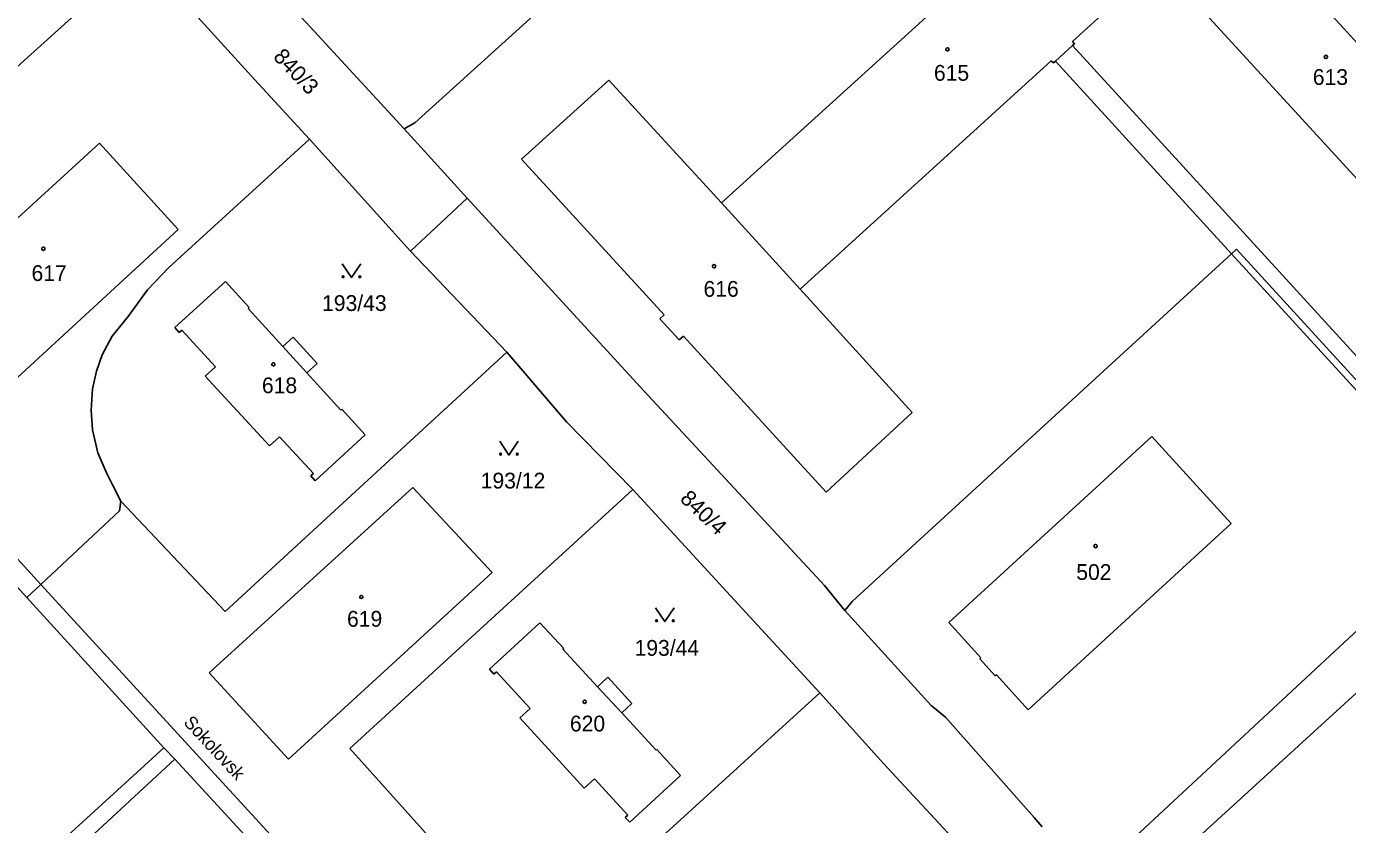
# Model space of a CAD drawing. Extents: x -735249 to -729401, y -1124843 to -1121828.
# Drawn here: x -733284.9 to -733142.5, y -1124173.7 to -1124087.8 of the extents above; entities that cross this region are included whole.
import ezdxf

# ---------------------------------------------------------------- set-up
doc = ezdxf.new("R2010")
doc.units = 0
for name, color, linetype in [('Vrstva 1', 7, 'Continuous'), ('Vrstva 15', 7, 'Continuous'), ('Vrstva 18', 7, 'Continuous'), ('Vrstva 19', 7, 'Continuous'), ('Vrstva 25', 7, 'Continuous'), ('Vrstva 4', 7, 'Continuous')]:
    doc.layers.add(name, color=color, linetype=linetype)

msp = doc.modelspace()

# ---------------------------------------------------------------- linework, layer by layer
at = {"layer": 'Vrstva 1'}
for points in [[(-733202.13, -1124061.12), (-733243.06, -1124098.12)], [(-733254.36, -1124087.81), (-733263.47, -1124077.99)], [(-733312.42, -1124115.94), (-733273.21, -1124080.62)], [(-733270.79, -1124081.95), (-733260.31, -1124093.51)], [(-733182.93, -1124082.16), (-733210.01, -1124106.74)], [(-733172.19, -1124089.37), (-733165.47, -1124083.25)], [(-733159.78, -1124084.25), (-733138.67, -1124107.29)], [(-733137.55, -1124093.86), (-733146.91, -1124083.63)], [(-733244.23, -1124098.79), (-733254.36, -1124087.81)], [(-733174.03, -1124091.48), (-733172.19, -1124089.81)], [(-733171.97, -1124089.61), (-733172.19, -1124089.37)], [(-733172.19, -1124089.81), (-733171.97, -1124089.61)], [(-733201.55, -1124116.06), (-733174.47, -1124091.44)], [(-733174.47, -1124091.44), (-733174.25, -1124091.68)], [(-733174.25, -1124091.68), (-733174.03, -1124091.48)], [(-733260.31, -1124093.51), (-733254.41, -1124099.91)], [(-733222.17, -1124093.52), (-733231.56, -1124102.06)], [(-733210.01, -1124106.74), (-733222.17, -1124093.52)], [(-733243.06, -1124098.12), (-733244.23, -1124098.79)], [(-733241.67, -1124101.59), (-733244.23, -1124098.79)], [(-733299.02, -1124120.41), (-733277.05, -1124100.32)], [(-733277.05, -1124100.32), (-733268.56, -1124109.63)], [(-733254.41, -1124099.91), (-733269.56, -1124113.73)], [(-733243.52, -1124111.95), (-733254.41, -1124099.91)], [(-733237.42, -1124106.23), (-733241.67, -1124101.59)], [(-733231.56, -1124102.06), (-733216.19, -1124118.83)], [(-733243.52, -1124111.95), (-733237.42, -1124106.23)], [(-733222.77, -1124122.22), (-733237.42, -1124106.23)], [(-733210.01, -1124106.74), (-733201.55, -1124116.06)], [(-733268.56, -1124109.63), (-733290.47, -1124129.75)], [(-733243.52, -1124111.95), (-733233.15, -1124122.85)], [(-733195.94, -1124149.7), (-733155.05, -1124112.23)], [(-733155.05, -1124112.23), (-733154.52, -1124111.75)], [(-733154.52, -1124111.75), (-733128.22, -1124140.46)], [(-733269.56, -1124113.73), (-733271.89, -1124116.11)], [(-733268.92, -1124120.18), (-733263.48, -1124115.21)], [(-733263.48, -1124115.21), (-733260.92, -1124118.02)], [(-733271.89, -1124116.11), (-733273.94, -1124119)], [(-733189.46, -1124129.35), (-733201.55, -1124116.06)], [(-733260.92, -1124118.02), (-733261.03, -1124118.12)], [(-733261.03, -1124118.12), (-733257.28, -1124122.23)], [(-733216.19, -1124118.83), (-733216.65, -1124119.25)], [(-733273.94, -1124119), (-733275.67, -1124121.11)], [(-733268.45, -1124120.7), (-733268.92, -1124120.18)], [(-733216.65, -1124119.25), (-733214.58, -1124121.52)], [(-733275.67, -1124121.11), (-733276.76, -1124123.12)], [(-733268.17, -1124120.45), (-733268.45, -1124120.7)], [(-733264.55, -1124124.4), (-733268.17, -1124120.45)], [(-733257.28, -1124122.23), (-733256.17, -1124121.22)], [(-733256.17, -1124121.22), (-733253.6, -1124124.04)], [(-733214.58, -1124121.52), (-733214.12, -1124121.1)], [(-733214.12, -1124121.1), (-733198.72, -1124137.91)], [(-733276.76, -1124123.12), (-733277.36, -1124124.89)], [(-733233.15, -1124122.85), (-733263.52, -1124150.78)], [(-733233.15, -1124122.85), (-733226.72, -1124130.35)], [(-733218.34, -1124127.05), (-733222.77, -1124122.22)], [(-733265.65, -1124125.41), (-733264.55, -1124124.4)], [(-733253.6, -1124124.04), (-733254.71, -1124125.05)], [(-733277.36, -1124124.89), (-733277.79, -1124126.77)], [(-733258.73, -1124132.92), (-733265.65, -1124125.41)], [(-733254.71, -1124125.05), (-733251.05, -1124129.07)], [(-733277.79, -1124126.77), (-733277.95, -1124129.1)], [(-733198.9, -1124147.98), (-733218.34, -1124127.05)], [(-733277.95, -1124129.1), (-733277.81, -1124131.2)], [(-733251.05, -1124129.07), (-733250.94, -1124128.97)], [(-733250.94, -1124128.97), (-733248.4, -1124131.75)], [(-733198.72, -1124137.91), (-733189.46, -1124129.35)], [(-733277.81, -1124131.2), (-733277.22, -1124133.67)], [(-733226.72, -1124130.35), (-733219.56, -1124137.63)], [(-733257.63, -1124131.95), (-733258.73, -1124132.92)], [(-733254, -1124135.91), (-733257.63, -1124131.95)], [(-733248.4, -1124131.75), (-733253.8, -1124136.68)], [(-733277.22, -1124133.67), (-733276.28, -1124135.85)], [(-733297.7, -1124135.21), (-733284.88, -1124149.26)], [(-733276.28, -1124135.85), (-733275.64, -1124137.14)], [(-733254.27, -1124136.16), (-733254, -1124135.91)], [(-733275.64, -1124137.14), (-733274.75, -1124138.87)], [(-733253.8, -1124136.68), (-733254.27, -1124136.16)], [(-733265.23, -1124157.36), (-733243.27, -1124137.42)], [(-733219.56, -1124137.63), (-733250.07, -1124165.54)], [(-733243.27, -1124137.42), (-733234.74, -1124146.56)], [(-733219.56, -1124137.63), (-733209.06, -1124149.07)], [(-733283.38, -1124147.86), (-733274.88, -1124139.91)], [(-733274.88, -1124139.91), (-733274.75, -1124138.87)], [(-733274.75, -1124138.87), (-733263.52, -1124150.78)], [(-733133.73, -1124145.58), (-733165.4, -1124175)], [(-733234.74, -1124146.56), (-733256.69, -1124166.69)], [(-733284.88, -1124149.26), (-733283.38, -1124147.86)], [(-733196.73, -1124150.66), (-733198.9, -1124147.98)], [(-733284.88, -1124149.26), (-733284.19, -1124150.02)], [(-733284.19, -1124150.02), (-733270.11, -1124165.44)], [(-733209.06, -1124149.07), (-733199.42, -1124159.53)], [(-733196.73, -1124150.66), (-733195.94, -1124149.7)], [(-733130.43, -1124149.37), (-733158.6, -1124175.09)], [(-733187.43, -1124160.89), (-733196.73, -1124150.66)], [(-733235.01, -1124156.99), (-733229.58, -1124151.98)], [(-733229.58, -1124151.98), (-733227.02, -1124154.75)], [(-733227.02, -1124154.75), (-733227.1, -1124154.82)], [(-733227.1, -1124154.82), (-733223.37, -1124158.87)], [(-733234.54, -1124157.51), (-733235.01, -1124156.99)], [(-733234.26, -1124157.26), (-733234.54, -1124157.51)], [(-733230.64, -1124161.21), (-733234.26, -1124157.26)], [(-733256.69, -1124166.69), (-733265.23, -1124157.36)], [(-733223.37, -1124158.87), (-733222.28, -1124157.86)], [(-733222.28, -1124157.86), (-733219.67, -1124160.69)], [(-733230.22, -1124187.57), (-733199.42, -1124159.53)], [(-733199.42, -1124159.53), (-733192.56, -1124167.15)], [(-733231.74, -1124162.24), (-733230.64, -1124161.21)], [(-733219.67, -1124160.69), (-733220.76, -1124161.69)], [(-733185.88, -1124162.16), (-733187.43, -1124160.89)], [(-733224.81, -1124169.8), (-733231.74, -1124162.24)], [(-733220.76, -1124161.69), (-733217.05, -1124165.71)], [(-733176.33, -1124172.97), (-733185.88, -1124162.16)], [(-733270.11, -1124165.44), (-733326.28, -1124216.71)], [(-733270.11, -1124165.44), (-733268.93, -1124166.67)], [(-733250.07, -1124165.54), (-733240.04, -1124176.68)], [(-733217.05, -1124165.71), (-733216.98, -1124165.65)], [(-733216.98, -1124165.65), (-733214.42, -1124168.42)], [(-733268.93, -1124166.67), (-733324.75, -1124218.3)], [(-733268.93, -1124166.67), (-733250.55, -1124186.65)], [(-733192.56, -1124167.15), (-733182.93, -1124177.51)], [(-733214.42, -1124168.42), (-733219.91, -1124173.47)], [(-733223.7, -1124168.78), (-733224.81, -1124169.8)], [(-733220.11, -1124172.7), (-733223.7, -1124168.78)], [(-733220.38, -1124172.95), (-733220.11, -1124172.7)], [(-733219.91, -1124173.47), (-733220.38, -1124172.95)], [(-733175.44, -1124173.98), (-733176.33, -1124172.97)]]:
    msp.add_lwpolyline(points, dxfattribs=at)
at = {"layer": 'Vrstva 25'}
for points in [[(-733250.9, -1124113.31), (-733249.9, -1124114.81), (-733248.9, -1124113.31)], [(-733233.92, -1124132.42), (-733232.92, -1124133.92), (-733231.92, -1124132.42)], [(-733217.11, -1124150.36), (-733216.11, -1124151.86), (-733215.11, -1124150.36)]]:
    msp.add_lwpolyline(points, dxfattribs=at)
for centre, radius in [((-733185.67, -1124090.22), 0.175), ((-733144.88, -1124091.03), 0.175), ((-733283.09, -1124111.7), 0.175), ((-733210.81, -1124113.58), 0.175), ((-733250.8, -1124114.71), 0.1), ((-733249, -1124114.71), 0.1), ((-733258.31, -1124124.15), 0.175), ((-733233.82, -1124133.82), 0.1), ((-733232.02, -1124133.82), 0.1), ((-733169.7, -1124143.72), 0.175), ((-733248.83, -1124149.21), 0.175), ((-733217.01, -1124151.76), 0.1), ((-733215.21, -1124151.76), 0.1), ((-733224.76, -1124160.49), 0.175)]:
    msp.add_circle(centre, radius, dxfattribs=at)
at = {"layer": 'Vrstva 4'}
for points in [[(-733126.94, -1124139.27), (-733172.19, -1124089.81)], [(-733174.03, -1124091.48), (-733155.05, -1124112.23)], [(-733155.05, -1124112.23), (-733128.77, -1124140.97)], [(-733312.42, -1124115.94), (-733283.38, -1124147.86)], [(-733257.28, -1124122.23), (-733254.71, -1124125.05)], [(-733185.5, -1124151.97), (-733163.63, -1124131.93)], [(-733163.63, -1124131.93), (-733155.1, -1124141.29)], [(-733155.1, -1124141.29), (-733176.96, -1124161.37)], [(-733249.06, -1124185.23), (-733283.38, -1124147.86)], [(-733182.06, -1124155.76), (-733185.5, -1124151.97)], [(-733182.18, -1124155.87), (-733182.06, -1124155.76)], [(-733180.52, -1124157.71), (-733182.18, -1124155.87)], [(-733180.39, -1124157.6), (-733180.52, -1124157.71)], [(-733176.96, -1124161.37), (-733180.39, -1124157.6)], [(-733223.37, -1124158.87), (-733220.76, -1124161.69)]]:
    msp.add_lwpolyline(points, dxfattribs=at)

# ---------------------------------------------------------------- texts
at = {"layer": 'Vrstva 15'}
msp.add_text('Sokolovsk\xa0', height=1.4, rotation=312.80249, dxfattribs=at).set_placement((-733268.068, -1124162.79))
at = {"layer": 'Vrstva 18'}
for s, rotation, p in [('840/3', 313.50249, (-733258.418, -1124091.107)), ('840/4', 316.60252, (-733214.588, -1124138.763))]:
    msp.add_text(s, height=1.7, rotation=rotation, dxfattribs=at).set_placement(p)
for s, p in [('193/43', (-733253.06, -1124118.4)), ('193/12', (-733235.96, -1124137.52)), ('193/44', (-733219.38, -1124155.54))]:
    msp.add_text(s, height=1.7, dxfattribs=at).set_placement(p)
at = {"layer": 'Vrstva 19'}
for s, p in [('615', (-733187.12, -1124093.6)), ('613', (-733146.29, -1124094.05)), ('617', (-733284.37, -1124115.17)), ('616', (-733211.95, -1124116.87)), ('618', (-733259.54, -1124127.26)), ('502', (-733171.78, -1124147.37)), ('619', (-733250.37, -1124152.41)), ('620', (-733226.35, -1124163.69))]:
    msp.add_text(s, height=1.7, dxfattribs=at).set_placement(p)

doc.saveas('drawing.dxf')
